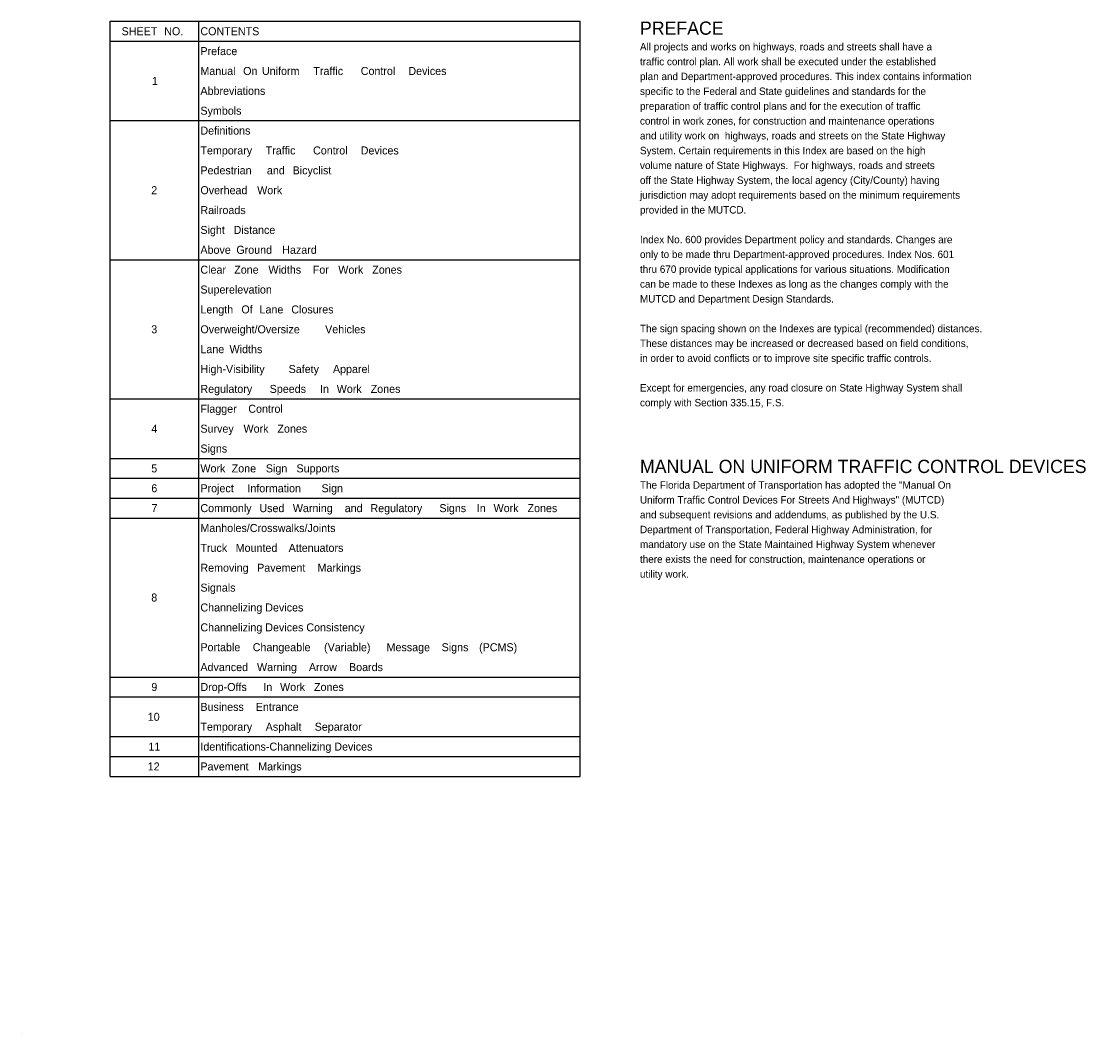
# Model space of a CAD drawing. Extents: x 10000 to 11261, y 10000 to 10478.
# Drawn here: x 10000 to 10502, y 10000 to 10478 of the extents above; entities that cross this region are included whole.
import ezdxf

# ---------------------------------------------------------------- set-up
doc = ezdxf.new("R2010")
doc.units = 0
for name, color, linetype in [('Patterning', 7, 'Continuous'), ('SumBoxLines_dp', 7, 'Continuous'), ('SupstrConc', 7, 'Continuous')]:
    doc.layers.add(name, color=color, linetype=linetype)

msp = doc.modelspace()

# ---------------------------------------------------------------- linework, layer by layer
at = {"layer": 'Patterning'}
msp.add_line((10000, 10000), (10000, 10000), dxfattribs=at)
at = {"layer": 'SumBoxLines_dp'}
for p, q in [((10042.01, 10121.46), (10042.01, 10477.91)), ((10042.01, 10477.91), (10263.79, 10477.91)), ((10083.89, 10121.46), (10083.89, 10477.91)), ((10263.79, 10121.46), (10263.79, 10477.91)), ((10042.01, 10468.53), (10263.79, 10468.53)), ((10042.01, 10431.01), (10263.79, 10431.01)), ((10042.01, 10365.35), (10263.79, 10365.35)), ((10042.01, 10299.69), (10263.79, 10299.69)), ((10042.01, 10271.55), (10263.79, 10271.55)), ((10042.01, 10262.17), (10263.79, 10262.17)), ((10042.01, 10252.79), (10263.79, 10252.79)), ((10042.01, 10243.41), (10263.79, 10243.41)), ((10042.01, 10168.36), (10263.79, 10168.36)), ((10042.01, 10158.98), (10263.79, 10158.98)), ((10042.01, 10140.22), (10263.79, 10140.22)), ((10042.01, 10130.84), (10263.79, 10130.84)), ((10042.01, 10121.46), (10263.79, 10121.46))]:
    msp.add_line(p, q, dxfattribs=at)
at = {"layer": 'SupstrConc'}
msp.add_line((10042.01, 10477.91), (10042.01, 10477.91), dxfattribs=at)

# ---------------------------------------------------------------- texts
for s, height, p in [('PREFACE', 6.25, (10292.07, 10471.56)), ('SHEET', 3.78, (10047.36, 10471.33)), (' NO.', 3.78, (10066.07, 10471.33)), ('CONTENTS', 3.78, (10084.56, 10471.33)), ('All projects and works on highways, roads and streets shall have a', 3.5, (10292.07, 10464.15)), ('Preface', 3.78, (10084.56, 10461.95)), ('traffic control plan. All work shall be executed under the established', 3.5, (10292.07, 10457.15)), ('Manual', 3.78, (10084.56, 10452.57)), (' On', 3.78, (10103.34, 10452.57)), (' Uniform', 3.78, (10112.23, 10452.57)), (' Traffic', 3.78, (10136.48, 10452.57)), (' Control', 3.78, (10158.85, 10452.57)), (' Devices', 3.78, (10181.33, 10452.57)), ('plan and Department-approved procedures. This index contains information', 3.5, (10292.07, 10450.15)), ('1', 3.78, (10061.7, 10447.88)), ('Abbreviations', 3.7796, (10084.56, 10443.19)), ('specific to the Federal and State guidelines and standards for the', 3.5, (10292.07, 10443.15)), ('Symbols', 3.78, (10084.56, 10433.81)), ('preparation of traffic control plans and for the execution of traffic', 3.5, (10292.07, 10436.15)), ('control in work zones, for construction and maintenance operations', 3.5, (10292.07, 10429.15)), ('Definitions', 3.7796, (10084.56, 10424.43)), ('and utility work on  highways, roads and streets on the State Highway', 3.5, (10292.07, 10422.15)), ('Temporary', 3.78, (10084.56, 10415.05)), (' Traffic', 3.78, (10113.98, 10415.05)), (' Control', 3.78, (10136.35, 10415.05)), (' Devices', 3.78, (10158.82, 10415.05)), ('System. Certain requirements in this Index are based on the high ', 3.5, (10292.07, 10415.15)), ('volume nature of State Highways.  For highways, roads and streets ', 3.5, (10292.07, 10408.15)), ('Pedestrian', 3.78, (10084.56, 10405.67)), (' and', 3.78, (10114.55, 10405.67)), (' Bicyclist', 3.78, (10126.69, 10405.67)), ('off the State Highway System, the local agency (City/County) having ', 3.5, (10292.07, 10401.15)), ('2', 3.78, (10061.36, 10396.29)), ('Overhead', 3.78, (10084.56, 10396.29)), (' Work', 3.78, (10109.96, 10396.29)), ('jurisdiction may adopt requirements based on the minimum requirements ', 3.5, (10292.07, 10394.15)), ('Railroads', 3.78, (10084.56, 10386.91)), ('provided in the MUTCD.', 3.5, (10292.07, 10387.15)), ('Sight', 3.78, (10084.56, 10377.53)), (' Distance', 3.78, (10098.84, 10377.53)), ('Index No. 600 provides Department policy and standards. Changes are ', 3.5, (10292.07, 10373.15)), ('Above', 3.78, (10084.56, 10368.15)), (' Ground', 3.78, (10100.12, 10368.15)), (' Hazard', 3.78, (10121.79, 10368.15)), ('only to be made thru Department-approved procedures. Index Nos. 601 ', 3.5, (10292.07, 10366.15)), ('Clear', 3.78, (10084.56, 10358.77)), (' Zone', 3.78, (10099.12, 10358.77)), (' Widths', 3.78, (10115.26, 10358.77)), (' For', 3.78, (10136.21, 10358.77)), (' Work', 3.78, (10148.25, 10358.77)), (' Zones', 3.78, (10164.26, 10358.77)), ('thru 670 provide typical applications for various situations. Modification ', 3.5, (10292.07, 10359.15)), ('Superelevation', 3.7796, (10084.56, 10349.39)), ('can be made to these Indexes as long as the changes comply with the ', 3.5, (10292.07, 10352.15)), ('MUTCD and Department Design Standards.', 3.5, (10292.07, 10345.15)), ('Length', 3.78, (10084.56, 10340.01)), (' Of', 3.78, (10102.49, 10340.01)), (' Lane', 3.78, (10111.07, 10340.01)), (' Closures', 3.78, (10126.07, 10340.01)), ('3', 3.78, (10061.36, 10330.63)), ('Overweight/Oversize', 3.7796, (10084.56, 10330.63)), (' Vehicles', 3.78, (10142.03, 10330.63)), ('The sign spacing shown on the Indexes are typical (recommended) distances.', 3.5, (10292.07, 10331.15)), ('These distances may be increased or decreased based on field conditions, ', 3.5, (10292.07, 10324.15)), ('Lane', 3.78, (10084.56, 10321.25)), (' Widths', 3.78, (10096.91, 10321.25)), ('in order to avoid conflicts or to improve site specific traffic controls.', 3.5, (10292.07, 10317.15)), ('High-Visibility', 3.7796, (10084.56, 10311.87)), (' Safety', 3.78, (10124.8, 10311.87)), (' Apparel', 3.78, (10145.73, 10311.87)), ('Regulatory', 3.78, (10084.56, 10302.49)), ('  Speeds', 3.78, (10114.45, 10302.49)), (' In', 3.78, (10139.62, 10302.49)), (' Work', 3.78, (10147.52, 10302.49)), (' Zones', 3.78, (10163.54, 10302.49)), ('Except for emergencies, any road closure on State Highway System shall', 3.5, (10292.07, 10303.15)), ('Flagger', 3.78, (10084.56, 10293.11)), (' Control', 3.78, (10105.76, 10293.11)), ('comply with Section 335.15, F.S.', 3.5, (10292.07, 10296.15)), ('4', 3.78, (10061.44, 10283.73)), ('Survey', 3.78, (10084.56, 10283.73)), (' Work', 3.78, (10103.51, 10283.73)), (' Zones', 3.78, (10119.52, 10283.73)), ('Signs', 3.78, (10084.56, 10274.35)), ('5', 3.78, (10061.38, 10264.97)), ('Work', 3.78, (10084.56, 10264.97)), (' Zone', 3.78, (10097.92, 10264.97)), (' Sign', 3.78, (10114.06, 10264.97)), (' Supports', 3.78, (10128.51, 10264.97)), ('MANUAL ON UNIFORM TRAFFIC CONTROL DEVICES', 6.25, (10292.07, 10264.67)), ('6', 3.78, (10061.4, 10255.59)), ('Project', 3.78, (10084.56, 10255.59)), (' Information', 3.7796, (10105.34, 10255.59)), (' Sign', 3.78, (10140.34, 10255.59)), ('The Florida Department of Transportation has adopted the "Manual On ', 3.5, (10292.07, 10257.26)), ('Uniform Traffic Control Devices For Streets And Highways" (MUTCD) ', 3.5, (10292.07, 10250.26)), ('7', 3.78, (10061.45, 10246.21)), ('Commonly', 3.78, (10084.56, 10246.21)), (' Used', 3.78, (10111.01, 10246.21)), (' Warning', 3.78, (10126.79, 10246.21)), (' and', 3.78, (10151.29, 10246.21)), (' Regulatory', 3.7796, (10163.43, 10246.21)), (' Signs', 3.78, (10195.97, 10246.21)), (' In', 3.78, (10213.65, 10246.21)), (' Work', 3.78, (10221.56, 10246.21)), (' Zones', 3.78, (10237.57, 10246.21)), ('and subsequent revisions and addendums, as published by the U.S. ', 3.5, (10292.07, 10243.26)), ('Manholes/Crosswalks/Joints', 3.7796, (10084.56, 10236.83)), ('Department of Transportation, Federal Highway Administration, for ', 3.5, (10292.07, 10236.26)), ('Truck', 3.78, (10084.56, 10227.45)), (' Mounted', 3.78, (10099.8, 10227.45)), (' Attenuators', 3.7796, (10124.81, 10227.45)), ('mandatory use on the State Maintained Highway System whenever ', 3.5, (10292.07, 10229.26)), ('there exists the need for construction, maintenance operations or ', 3.5, (10292.07, 10222.26)), ('Removing', 3.78, (10084.56, 10218.07)), (' Pavement', 3.78, (10109.95, 10218.07)), (' Markings', 3.78, (10138.46, 10218.07)), ('utility work.', 3.5, (10292.07, 10215.26)), ('Signals', 3.78, (10084.56, 10208.69)), ('8', 3.78, (10061.37, 10204.02)), ('Channelizing Devices', 3.7796, (10084.56, 10199.31)), ('Channelizing Devices Consistency', 3.7796, (10084.56, 10189.93)), ('Portable', 3.78, (10084.56, 10180.55)), (' Changeable', 3.7796, (10107.86, 10180.55)), (' (Variable)', 3.7796, (10141.54, 10180.55)), (' Message', 3.78, (10171.04, 10180.55)), (' Signs', 3.78, (10197.04, 10180.55)), (' (PCMS)', 3.78, (10214.72, 10180.55)), ('Advanced', 3.78, (10084.56, 10171.17)), (' Warning', 3.78, (10109.89, 10171.17)), (' Arrow', 3.78, (10134.38, 10171.17)), (' Boards', 3.78, (10153.31, 10171.17)), ('9', 3.78, (10061.4, 10161.78)), ('Drop-Offs', 3.78, (10084.56, 10161.78)), (' In', 3.78, (10112.86, 10161.78)), (' Work', 3.78, (10120.76, 10161.78)), (' Zones', 3.78, (10136.78, 10161.78)), ('Business', 3.78, (10084.56, 10152.4)), (' Entrance', 3.78, (10109.28, 10152.4)), ('10', 3.78, (10059.71, 10147.71)), ('Temporary', 3.78, (10084.56, 10143.02)), (' Asphalt', 3.78, (10113.98, 10143.02)), (' Separator', 3.78, (10137.1, 10143.02)), ('11', 3.78, (10060.01, 10133.64)), ('Identifications-Channelizing Devices', 3.7796, (10084.56, 10133.64)), ('12', 3.78, (10059.67, 10124.26)), ('Pavement', 3.78, (10084.56, 10124.26)), (' Markings', 3.78, (10110.42, 10124.26))]:
    msp.add_text(s, height=height, dxfattribs=at).set_placement(p)

doc.saveas('drawing.dxf')
